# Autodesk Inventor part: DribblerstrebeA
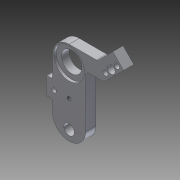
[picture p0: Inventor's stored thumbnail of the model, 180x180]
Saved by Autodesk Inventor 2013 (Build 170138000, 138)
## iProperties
Created: 2012-07
Part Number: DribblerstrebeA
Material: Aluminium 6061
Document SubType Name: Modeling
Designer: rYan
Mass: 4.21885 g
Surface Area: 15.9956 cm^2
Volume: 1.55677 cm^3
Density: 2.71 g/cm^3
d0: 13,000 mm
d8: 4,000 mm
d9: 0,00 grd
d10: 4,100 mm
d17: 8,000 mm
d19: 12,000 mm
d20: 1,000 mm
d24: 6,000 mm
Author: rYan
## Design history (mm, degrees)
sketch "Skizze1"
  geometry: L1 (6.5, 26.5)-(-11.124, 26.5); L2 (-11.124, 26.5)-(-17.167, 32.543); L3 (-17.167, 32.543)-(-21.41, 28.3); L4 (-21.41, 28.3)-(-13.61, 20.5); L5 (-13.61, 20.5)-(-6.5, 20.5); L6 (-6.5, 20.5)-(-6.5, 0); L7 (0, -17.628)-(0, 60.267) reference; L8 (-27.513, 0)-(15.206, 0) reference; L9 (5.332, -6.5)-(-6.5, -6.5); L10 (-13.632, 29.007)-(-5.5, 37.139); L11 (6.5, 0)-(6.5, 4); L12 (6.5, 12)-(6.5, 26.5); L13 (9, 11)-(9, 5); L14 (7, 11.5)-(8.5, 11.5); L15 (7, 4.5)-(8.5, 4.5); L16 (9, 8)-(0, 8); C1 r 6.5 at (0, 20); C2 r 6 at (0, 20); C3 r 12 at (-5.5, 37.139); A1 r 6.5 centre (0, 0) between (-6.5, 0) and (6.5, 0); A2 r 0.5 centre (7, 12) between (6.5, 12) and (7, 11.5); A3 r 0.5 centre (7, 4) between (7, 4.5) and (6.5, 4); A4 r 0.5 centre (8.5, 11) between (9, 11) and (8.5, 11.5); A5 r 0.5 centre (8.5, 5) between (8.5, 4.5) and (9, 5); 2 further points
  constraints: 28 end point, 20 tangent, 10 point on circle, 8 centre point, 7 parallel, 6 perpendicular, 4 point on line, 3 coincident, 2 vertical, 1 midpoint
  dimensions: "d24" = 6 distance of L2.end L3.end; "d26" = 6 distance between parallel lines of L1 L5; "d41" = 45 deg angle of L2 L1; "d48" = 4 distance from line of point (0, -2.5) L9; "d49" = 12 diameter of C2; "d51" = 5 distance between parallel lines of L10 L3; "d52" = 24 diameter of C3; "d67" = 22.5 distance of point (0, -2.5) C1.centre; "d68" = 17.5 distance from line of L10.end L4; "d69" = 0.5 radius of A2; "d70" = 0.5 radius of A3; "d74" = 13 distance between parallel lines of L6 L12; "d89" = 0.5 radius of A4; "d90" = 0.5 radius of A5; "d91" = 7 distance between parallel lines of L15 L14; "d92" = 9 distance between parallel lines of L7 L13; "d93" = 8 distance between parallel lines of L8 L16
extrude "Extrusion1" new body sketch "Skizze1" distance "d8" = 4; taper "d9" = 0 deg
sketch "Skizze2"
  geometry: L1 (0, 40.352)-(0, -14.309) reference; L2 (-6, -6.5)-(6, -6.5); A1 r 6.5 centre (0, 0) between (6.5, 0) and (-6.5, 0) reference; 2 further points
  constraints: 2 end point, 1 perpendicular, 1 point on line, 1 tangent
  dimensions: "d27" = 4 distance from line of L2 point (0, -2.5)
hole "Bohrung1" sketch "Skizze2" diameter "d10" = 4.1; stored, may be unused: countersink angle "d14" = 90 deg, drill point angle "d16" = 118 deg; dims "d11" = 6, "d12" = 4, "d13" = 2, "d15" = 8
sketch "Skizze3"
  geometry: L1 (11.124, 26.5)-(-6.5, 26.5) reference; L2 (-6.5, 26.5)-(-6.5, 0) reference; L3 (6.5, 0)-(6.5, 20.5) reference; L4 (6.5, 20.5)-(6.5, 26.5); C1 r 6.5 at (0, 20); 2 further points
  constraints: 3 tangent, 2 end point, 1 centre point, 1 coincident, 1 perpendicular, 1 point on line
hole "Bohrung2" sketch "Skizze3" at (0, 20) diameter "d17" = 8; stored, may be unused: countersink angle "d21" = 90 deg, drill point angle "d23" = 118 deg; dims "d18" = 6, "d19" = 12, "d20" = 1, "d22" = 8
fillet "Rundung1" dims "d42" = 6.5
fillet "Rundung2" dims "d43" = 1
fillet "Rundung3" dims "d44" = 1
sketch "Skizze6"
  geometry: L1 (17.167, -32.543)-(21.41, -28.3) reference; L2 (21.41, -28.3)-(13.902, -20.793) reference; L3 (11.417, -26.793)-(17.167, -32.543) reference; L4 (13.195, -20.5)-(7.5, -20.5) reference; L5 (19.996, -29.715)-(10.781, -20.5); 2 further points
  constraints: 3 point on line, 2 end point, 1 parallel
  dimensions: "d109" = 2 distance between parallel lines of L2 L5; "d110" = 5 distance from line of L1 point (16.46, -26.179)
hole "Bohrung4" sketch "Skizze6" at (16.46, -26.179) diameter "d60" = 3.2; stored, may be unused: countersink angle "d64" = 90 deg, drill point angle "d66" = 118 deg; dims "d61" = 6, "d62" = 4, "d63" = 2, "d65" = 8
sketch "Skizze8"
  geometry: L1 (-1.8, -5.5)-(-9.5, -5.5); L2 (-9.5, -5.5)-(-9.5, -10.5); L3 (-9.5, -10.5)-(-1.8, -10.5); L4 (-1.8, -10.5)-(-1.8, -5.5); L5 (-9, -5)-(-9, -11) reference; L6 (0, 14.309)-(0, -40.352) reference; L7 (-9, -8)-(0, -8); C1 r 2.5 at (-6, -8); 1 further point
  constraints: 10 end point, 2 parallel, 2 perpendicular, 2 point on line, 2 tangent, 1 centre point, 1 horizontal, 1 midpoint
  dimensions: "d82" = 5 distance of L1.end L2.end; "d84" = 7.7 distance of L1.start L1.end; "d94" = 6 distance from line of C1.centre L6; "d120" = 1.8 distance between parallel lines of L6 L4
extrude "Extrusion3" cut sketch "Skizze8" distance "d85" = 2; taper "d86" = 0 deg
fillet "Rundung4" dims "d95" = 0.5
sketch "Skizze9"
  geometry: L1 (0, 14.309)-(0, -40.352) reference; L2 (-9, -10.5)-(-9, -5.5) reference; L3 (-9, -8)-(0, -8); 1 further point
  constraints: 2 end point, 1 midpoint, 1 perpendicular, 1 point on line
hole "Bohrung6" sketch "Skizze9" at (0, -8) diameter "d97" = 1.567; stored, may be unused: countersink angle "d101" = 90 deg, drill point angle "d103" = 118 deg; dims "d98" = 6, "d99" = 4, "d100" = 2, "d102" = 8
sketch "Skizze10"
  geometry: L1 (0, 14.309)-(0, -40.352) reference; L2 (-9, -5.5)-(-2.3, -5.5) reference; L3 (-2.3, -10.5)-(-9, -10.5) reference; C1 r 2.5 at (-6, -8); 1 further point
  constraints: 2 tangent, 1 centre point
  dimensions: "d105" = 6 distance from line of L1 C1.centre
sketch "Skizze11"
  geometry: L1 (21.41, -28.3)-(13.902, -20.793) reference; L2 (17.167, -32.543)-(21.41, -28.3) reference; L3 (11.417, -26.793)-(17.167, -32.543) reference; L4 (13.195, -20.5)-(7.5, -20.5) reference; L5 (19.996, -29.715)-(10.781, -20.5); C1 r 1.6 at (16.46, -26.179) reference; 3 further points
  constraints: 5 point on line, 2 end point, 1 parallel
  dimensions: "d111" = 1.8 distance from line of point (18.723, -28.442) L2; "d112" = 6.4 distance of point (18.723, -28.442) point (14.197, -23.916)
hole "Bohrung7" sketch "Skizze11" at (18.723, -28.442), (14.197, -23.916) diameter "d113" = 2.1; stored, may be unused: countersink angle "d117" = 90 deg, drill point angle "d119" = 118 deg; dims "d114" = 6, "d115" = 4, "d116" = 2, "d118" = 8
hole "Bohrung8" sketch "Skizze10" diameter "d121" = 2; stored, may be unused: countersink angle "d125" = 90 deg, drill point angle "d127" = 118 deg; dims "d122" = 6, "d123" = 3.5, "d124" = 1, "d126" = 8
node "Volumenkörper1"
other parameters: "d0" = 13
